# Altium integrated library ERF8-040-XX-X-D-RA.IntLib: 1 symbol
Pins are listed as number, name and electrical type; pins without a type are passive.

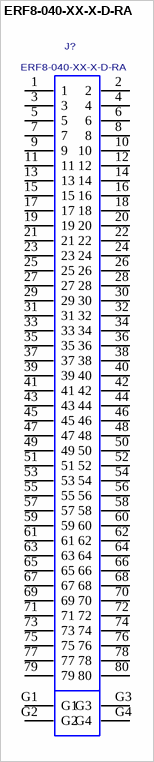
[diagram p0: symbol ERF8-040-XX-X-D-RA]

## ERF8-040-XX-X-D-RA
designator J?
0.8MM PITCH DUAL ROW RIGHT ANGLE SOCKET ASSEMBLY.; MANUFACTURER: SAMTEC
footprint ERF8-040-XX-X-D-RA
pins: 1, 2, 3, 4, 5, 6, 7, 8, 9, 10, 11, 12, 13, 14, 15, 16, 17, 18, 19, 20, 21, 22, 23, 24, 25, 26, 27, 28, 29, 30, 31, 32, 33, 34, 35, 36, 37, 38, 39, 40, 41, 42, 43, 44, 45, 46, 47, 48, 49, 50, 51, 52, 53, 54, 55, 56, 57, 58, 59, 60, 61, 62, 63, 64, 65, 66, 67, 68, 69, 70, 71, 72, 73, 74, 75, 76, 77, 78, 79, 80, G1, G2, G3, G4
